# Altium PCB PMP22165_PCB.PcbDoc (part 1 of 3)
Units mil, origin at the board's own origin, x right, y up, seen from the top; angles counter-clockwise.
Board outline 3700 x 3000 mil, 4 copper layers (Top Layer, Signal Layer 1, Signal Layer 2, Bottom Layer), stack 61.634 mil thick; 232 components, 104 nets, 594 pads, 232 vias.
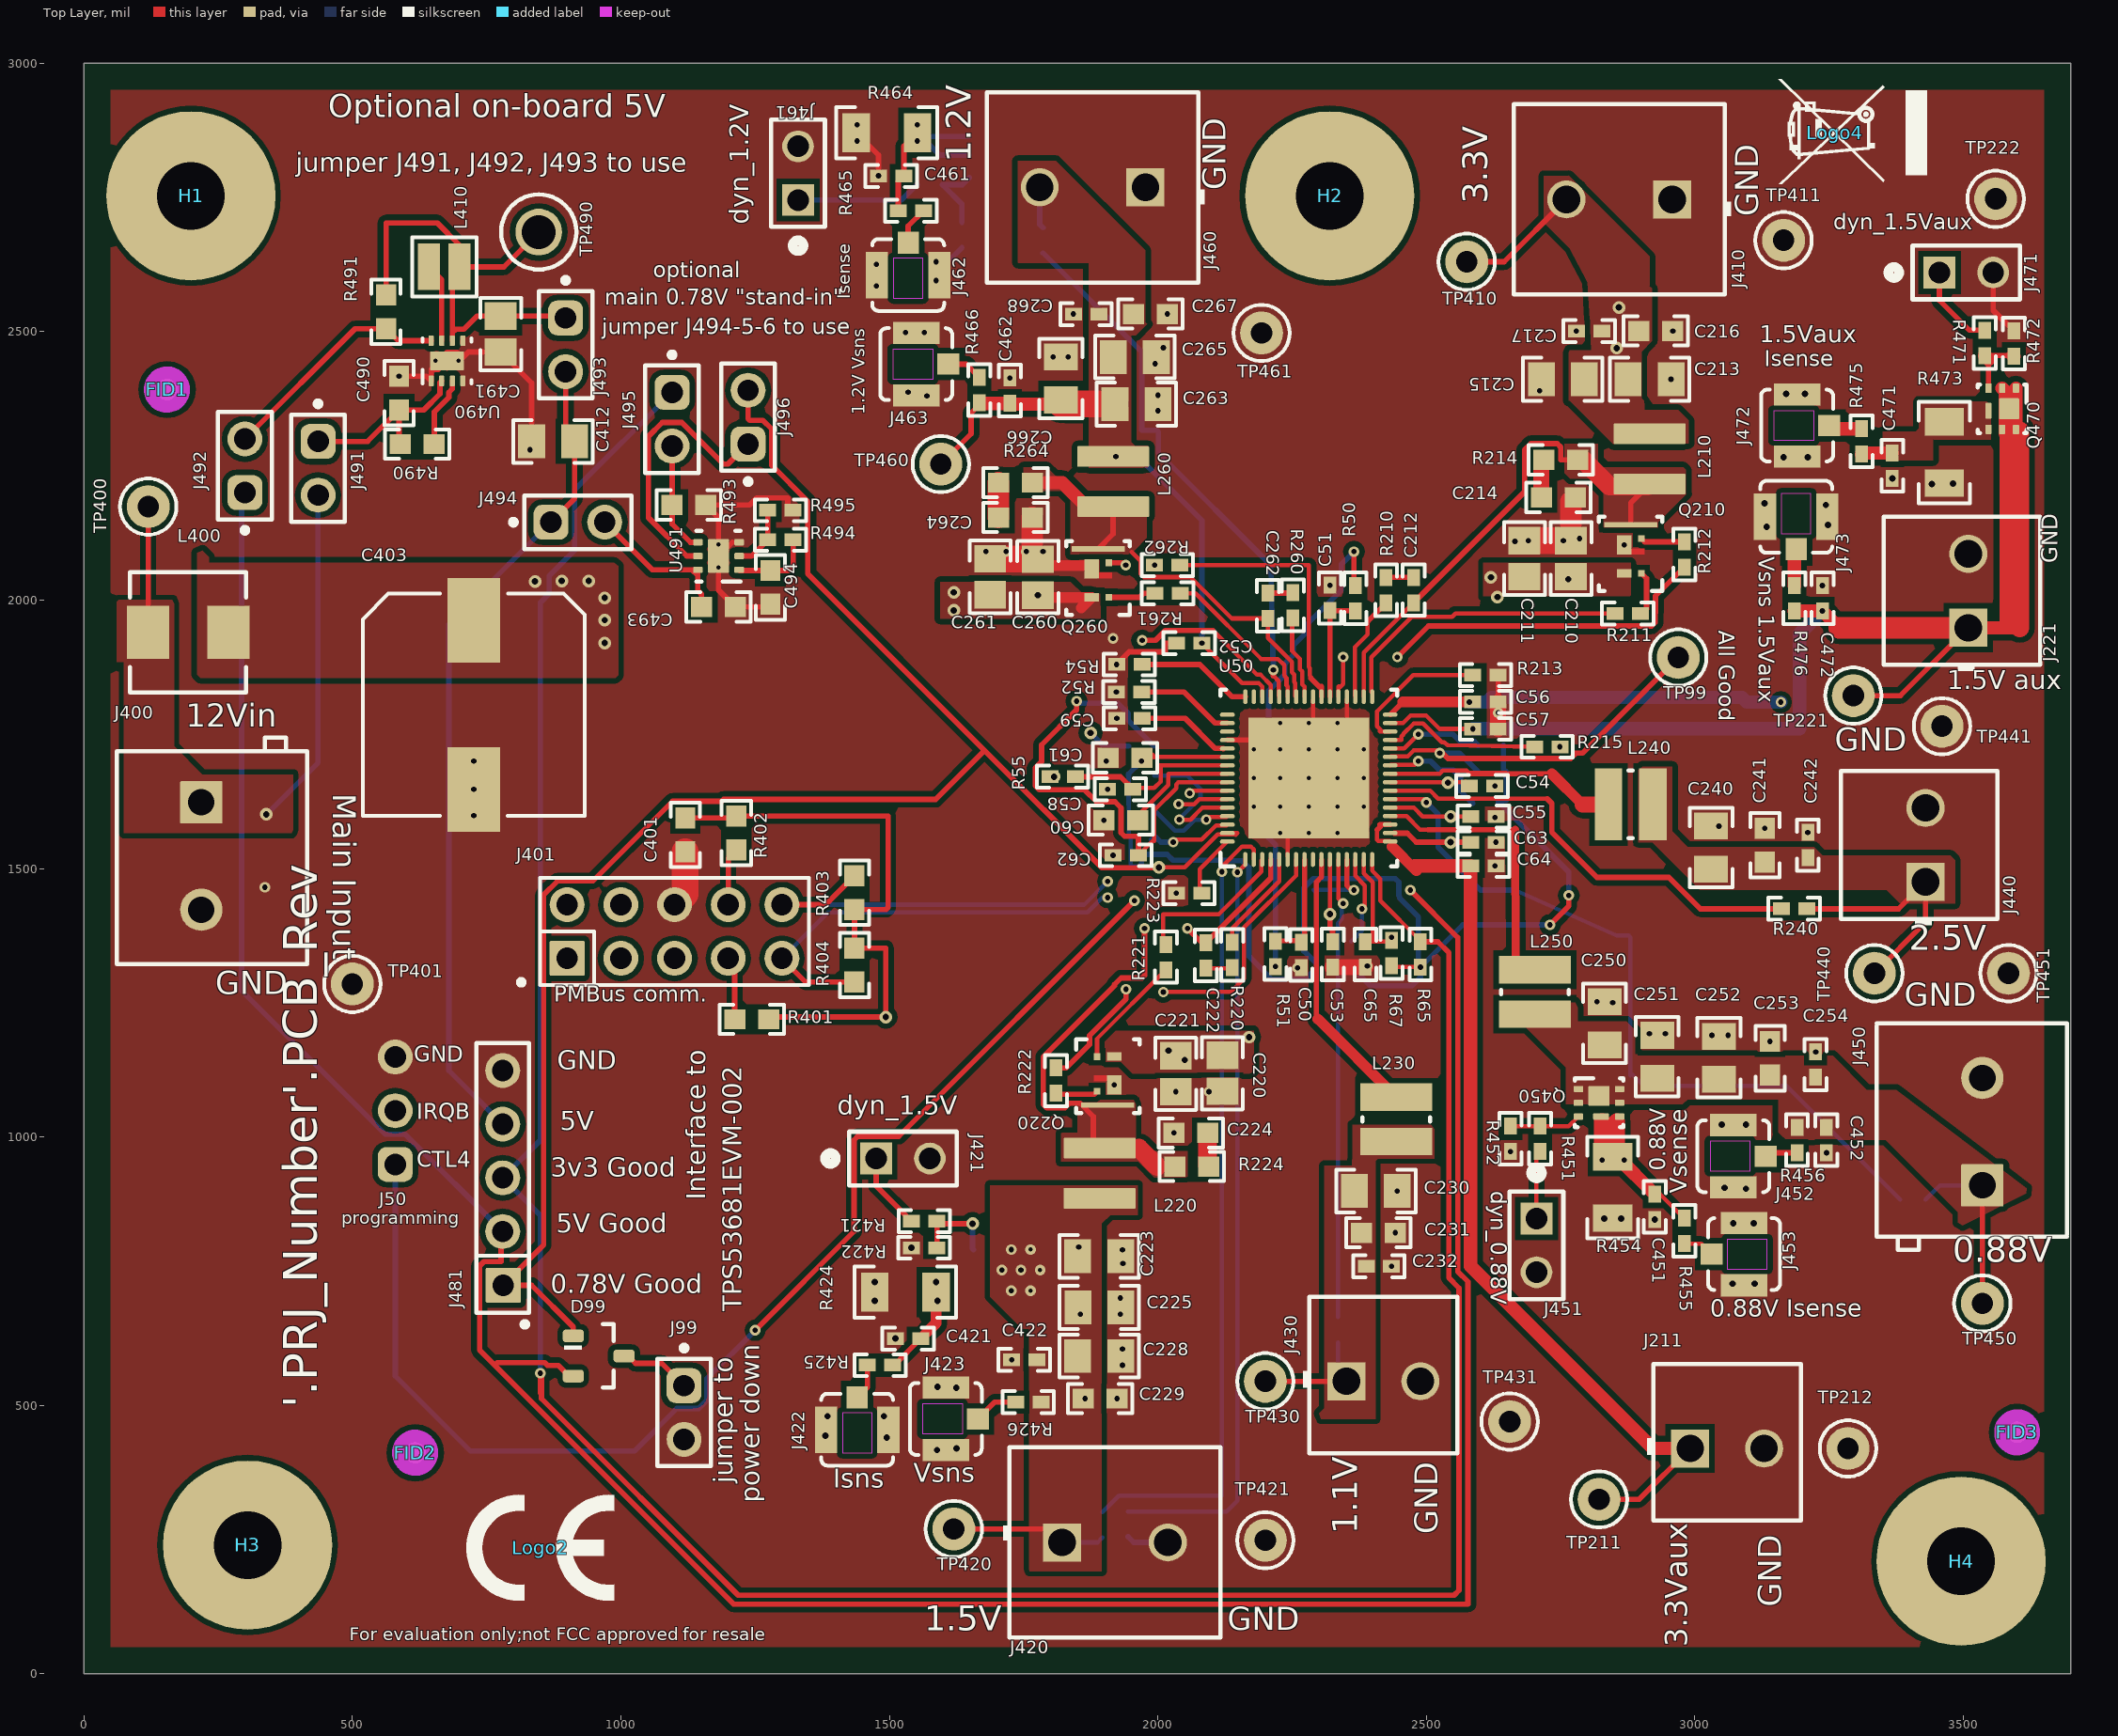
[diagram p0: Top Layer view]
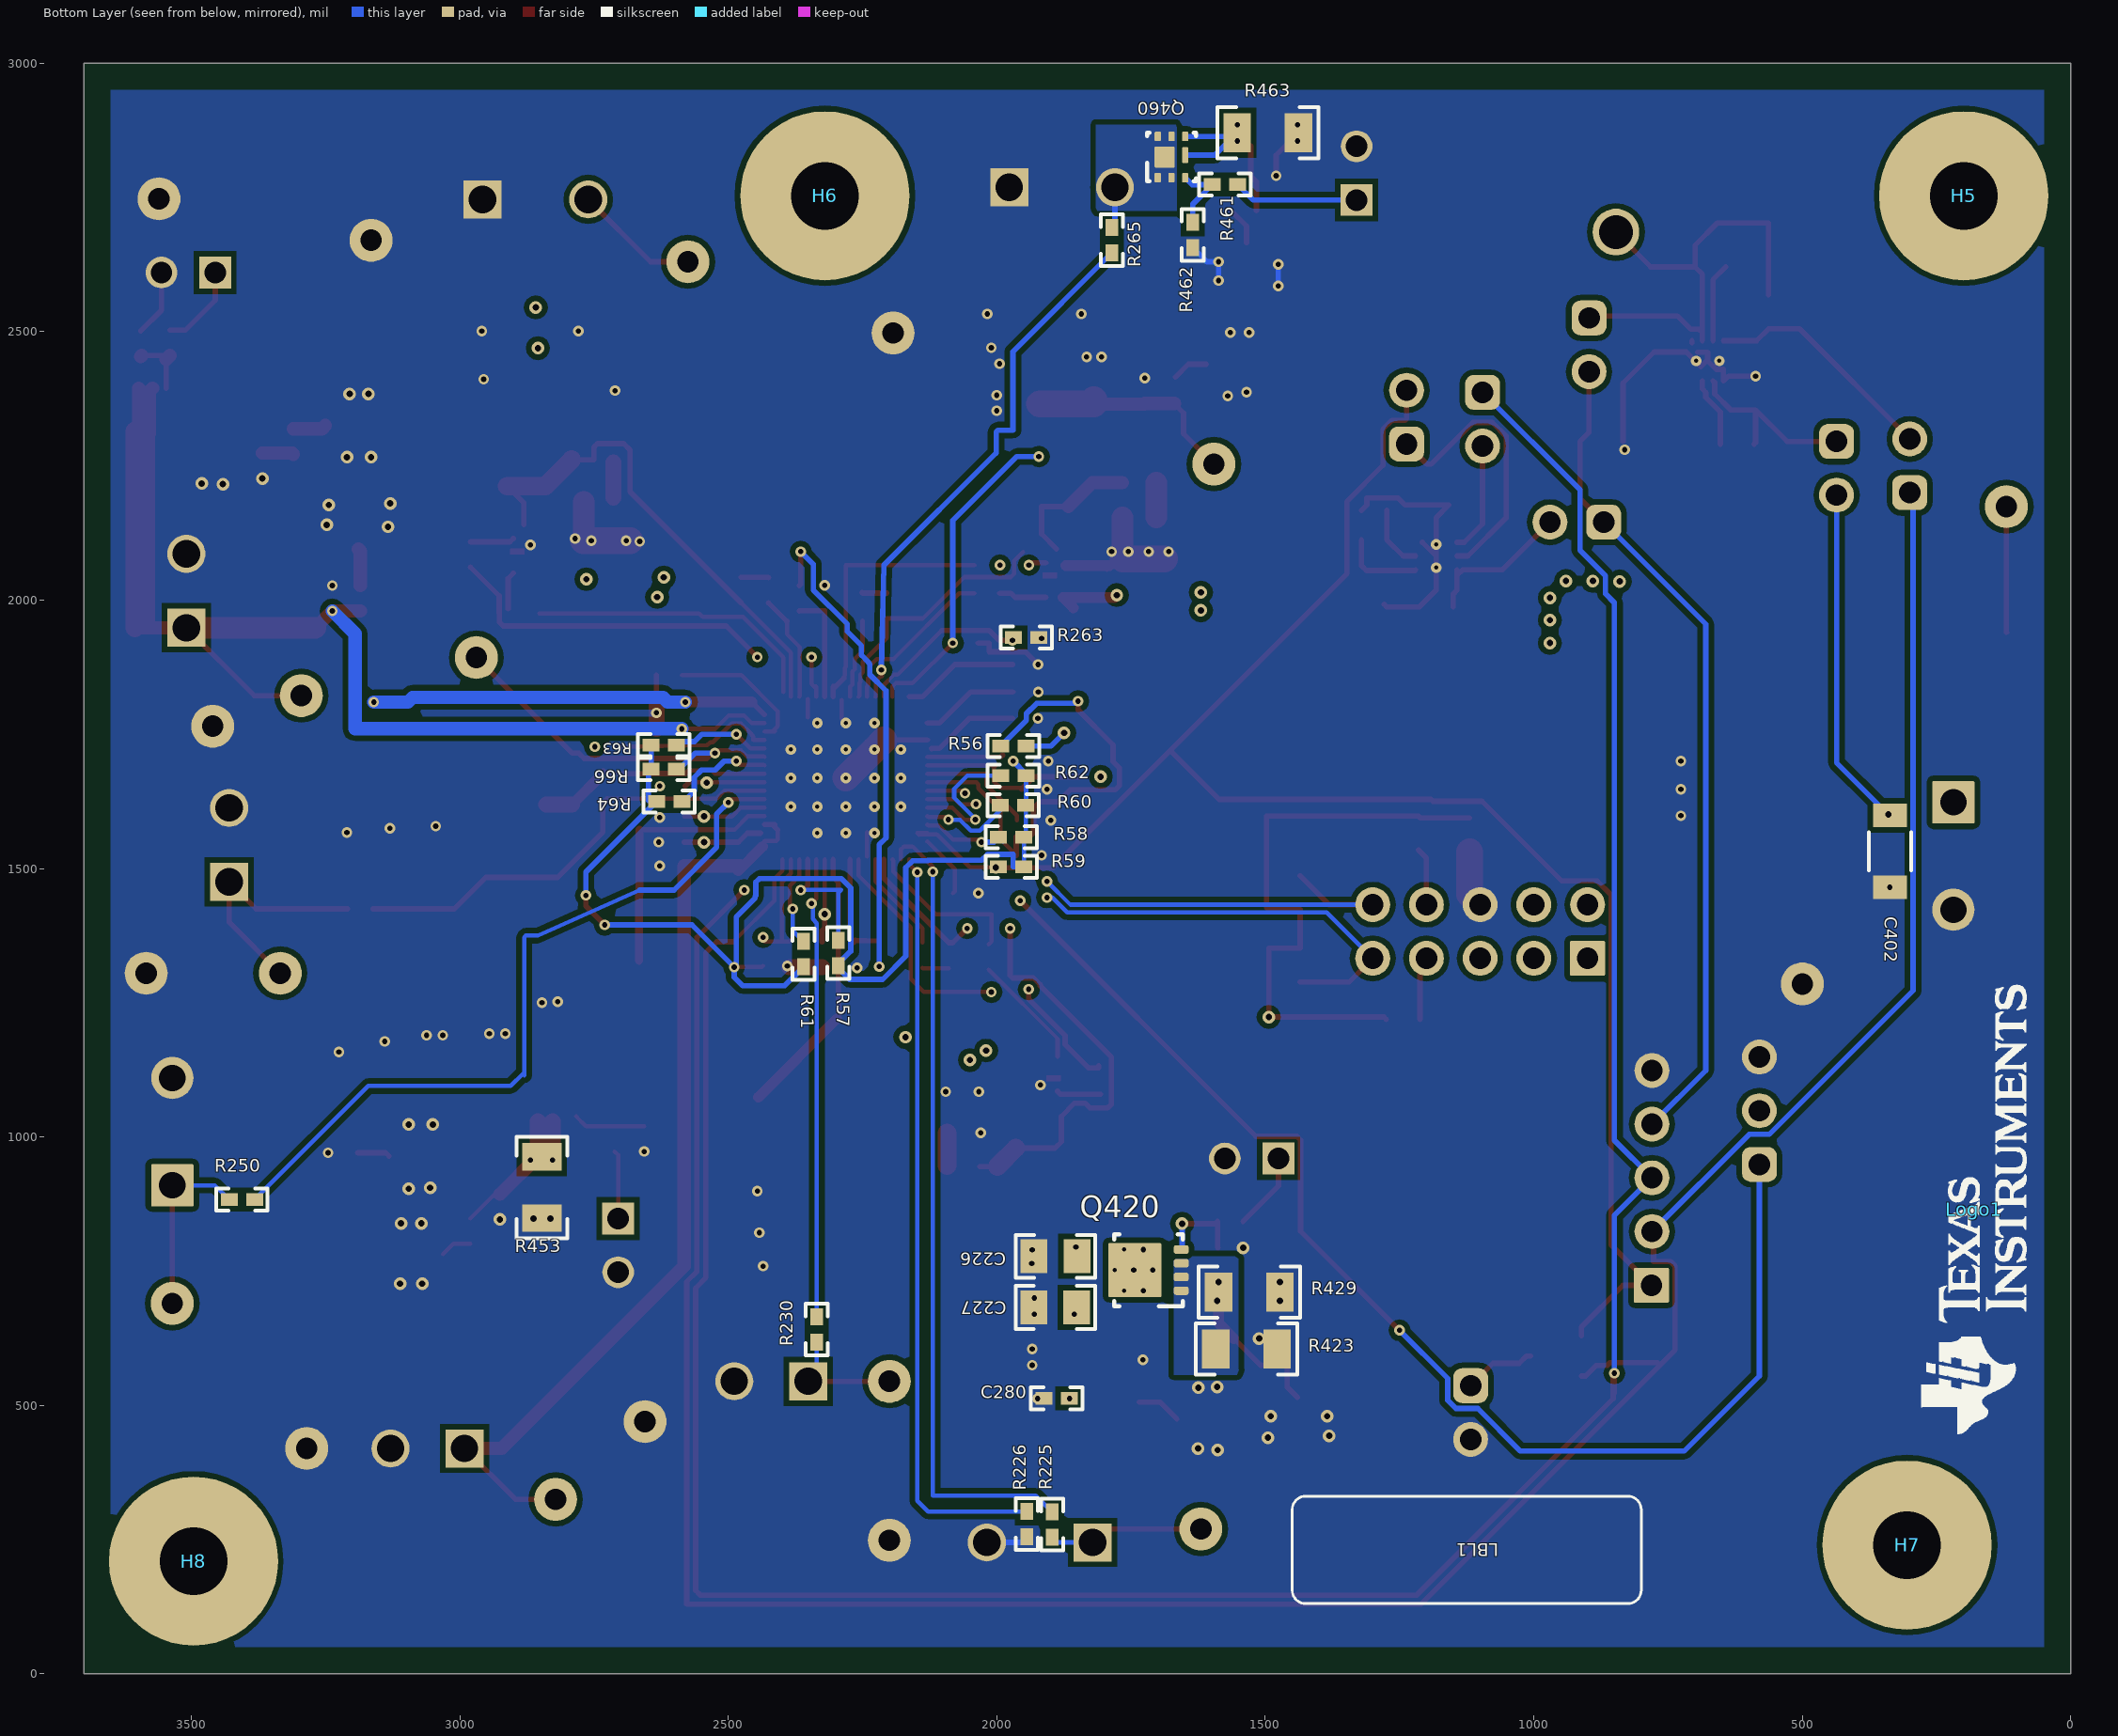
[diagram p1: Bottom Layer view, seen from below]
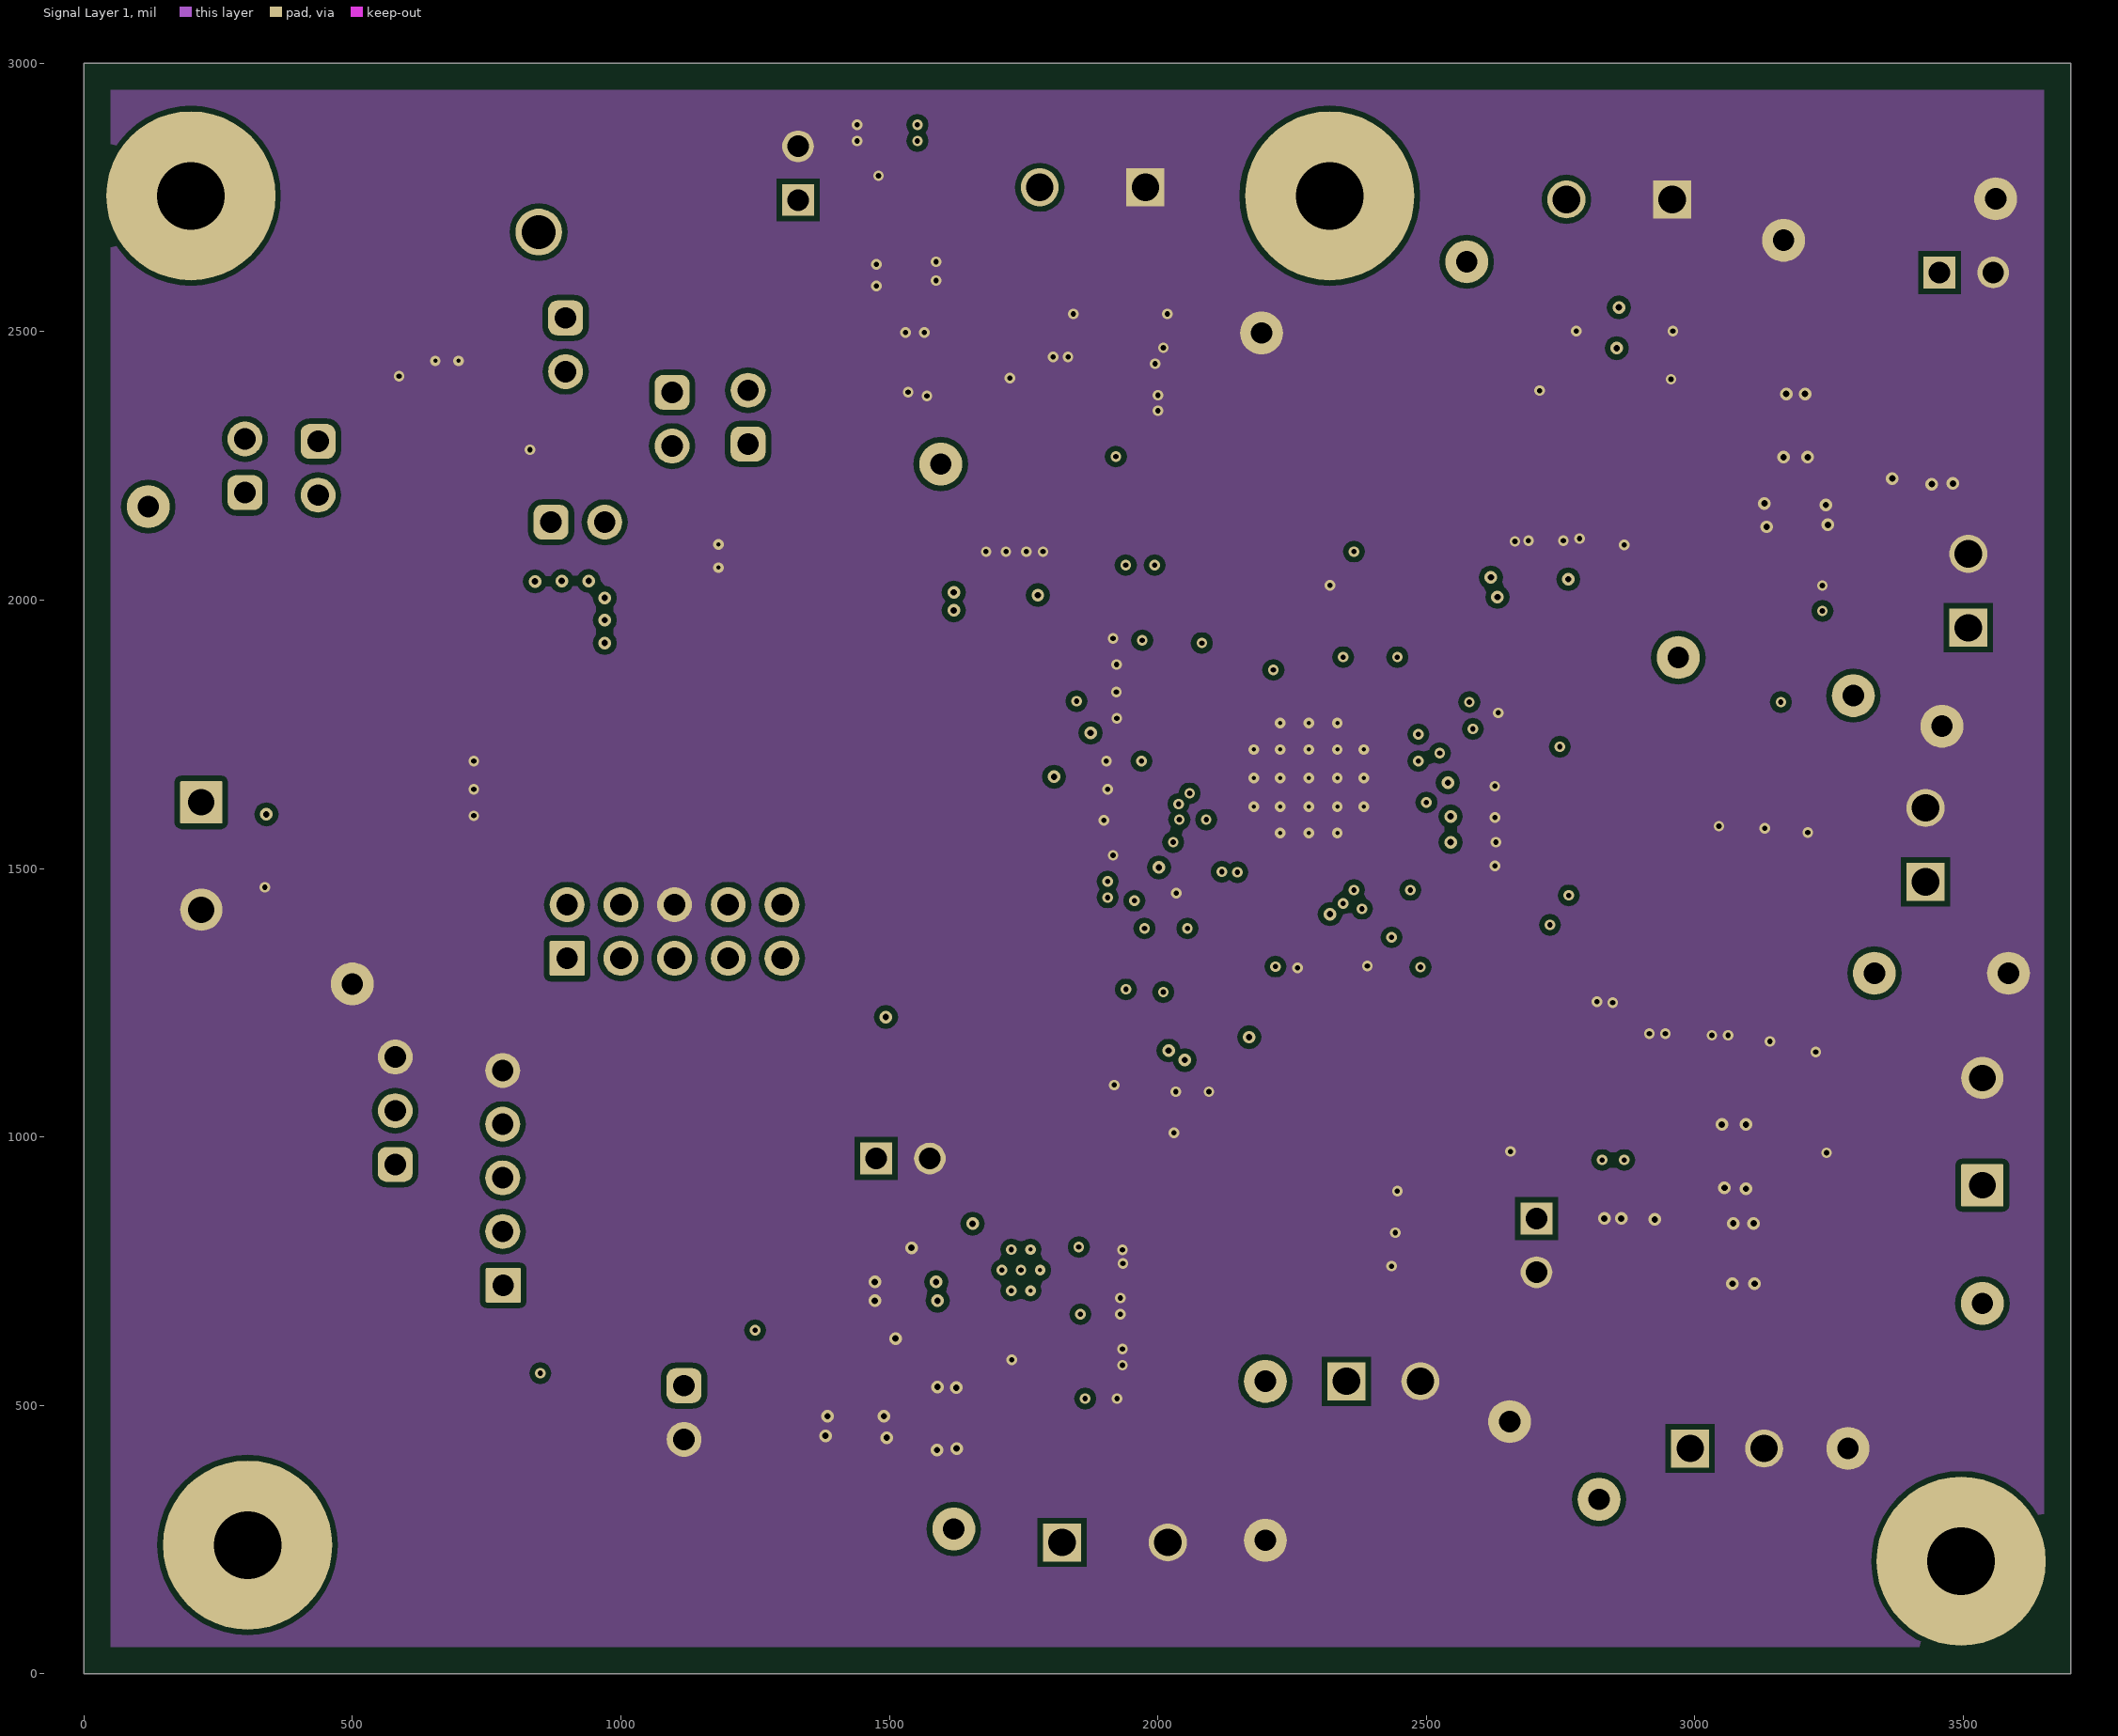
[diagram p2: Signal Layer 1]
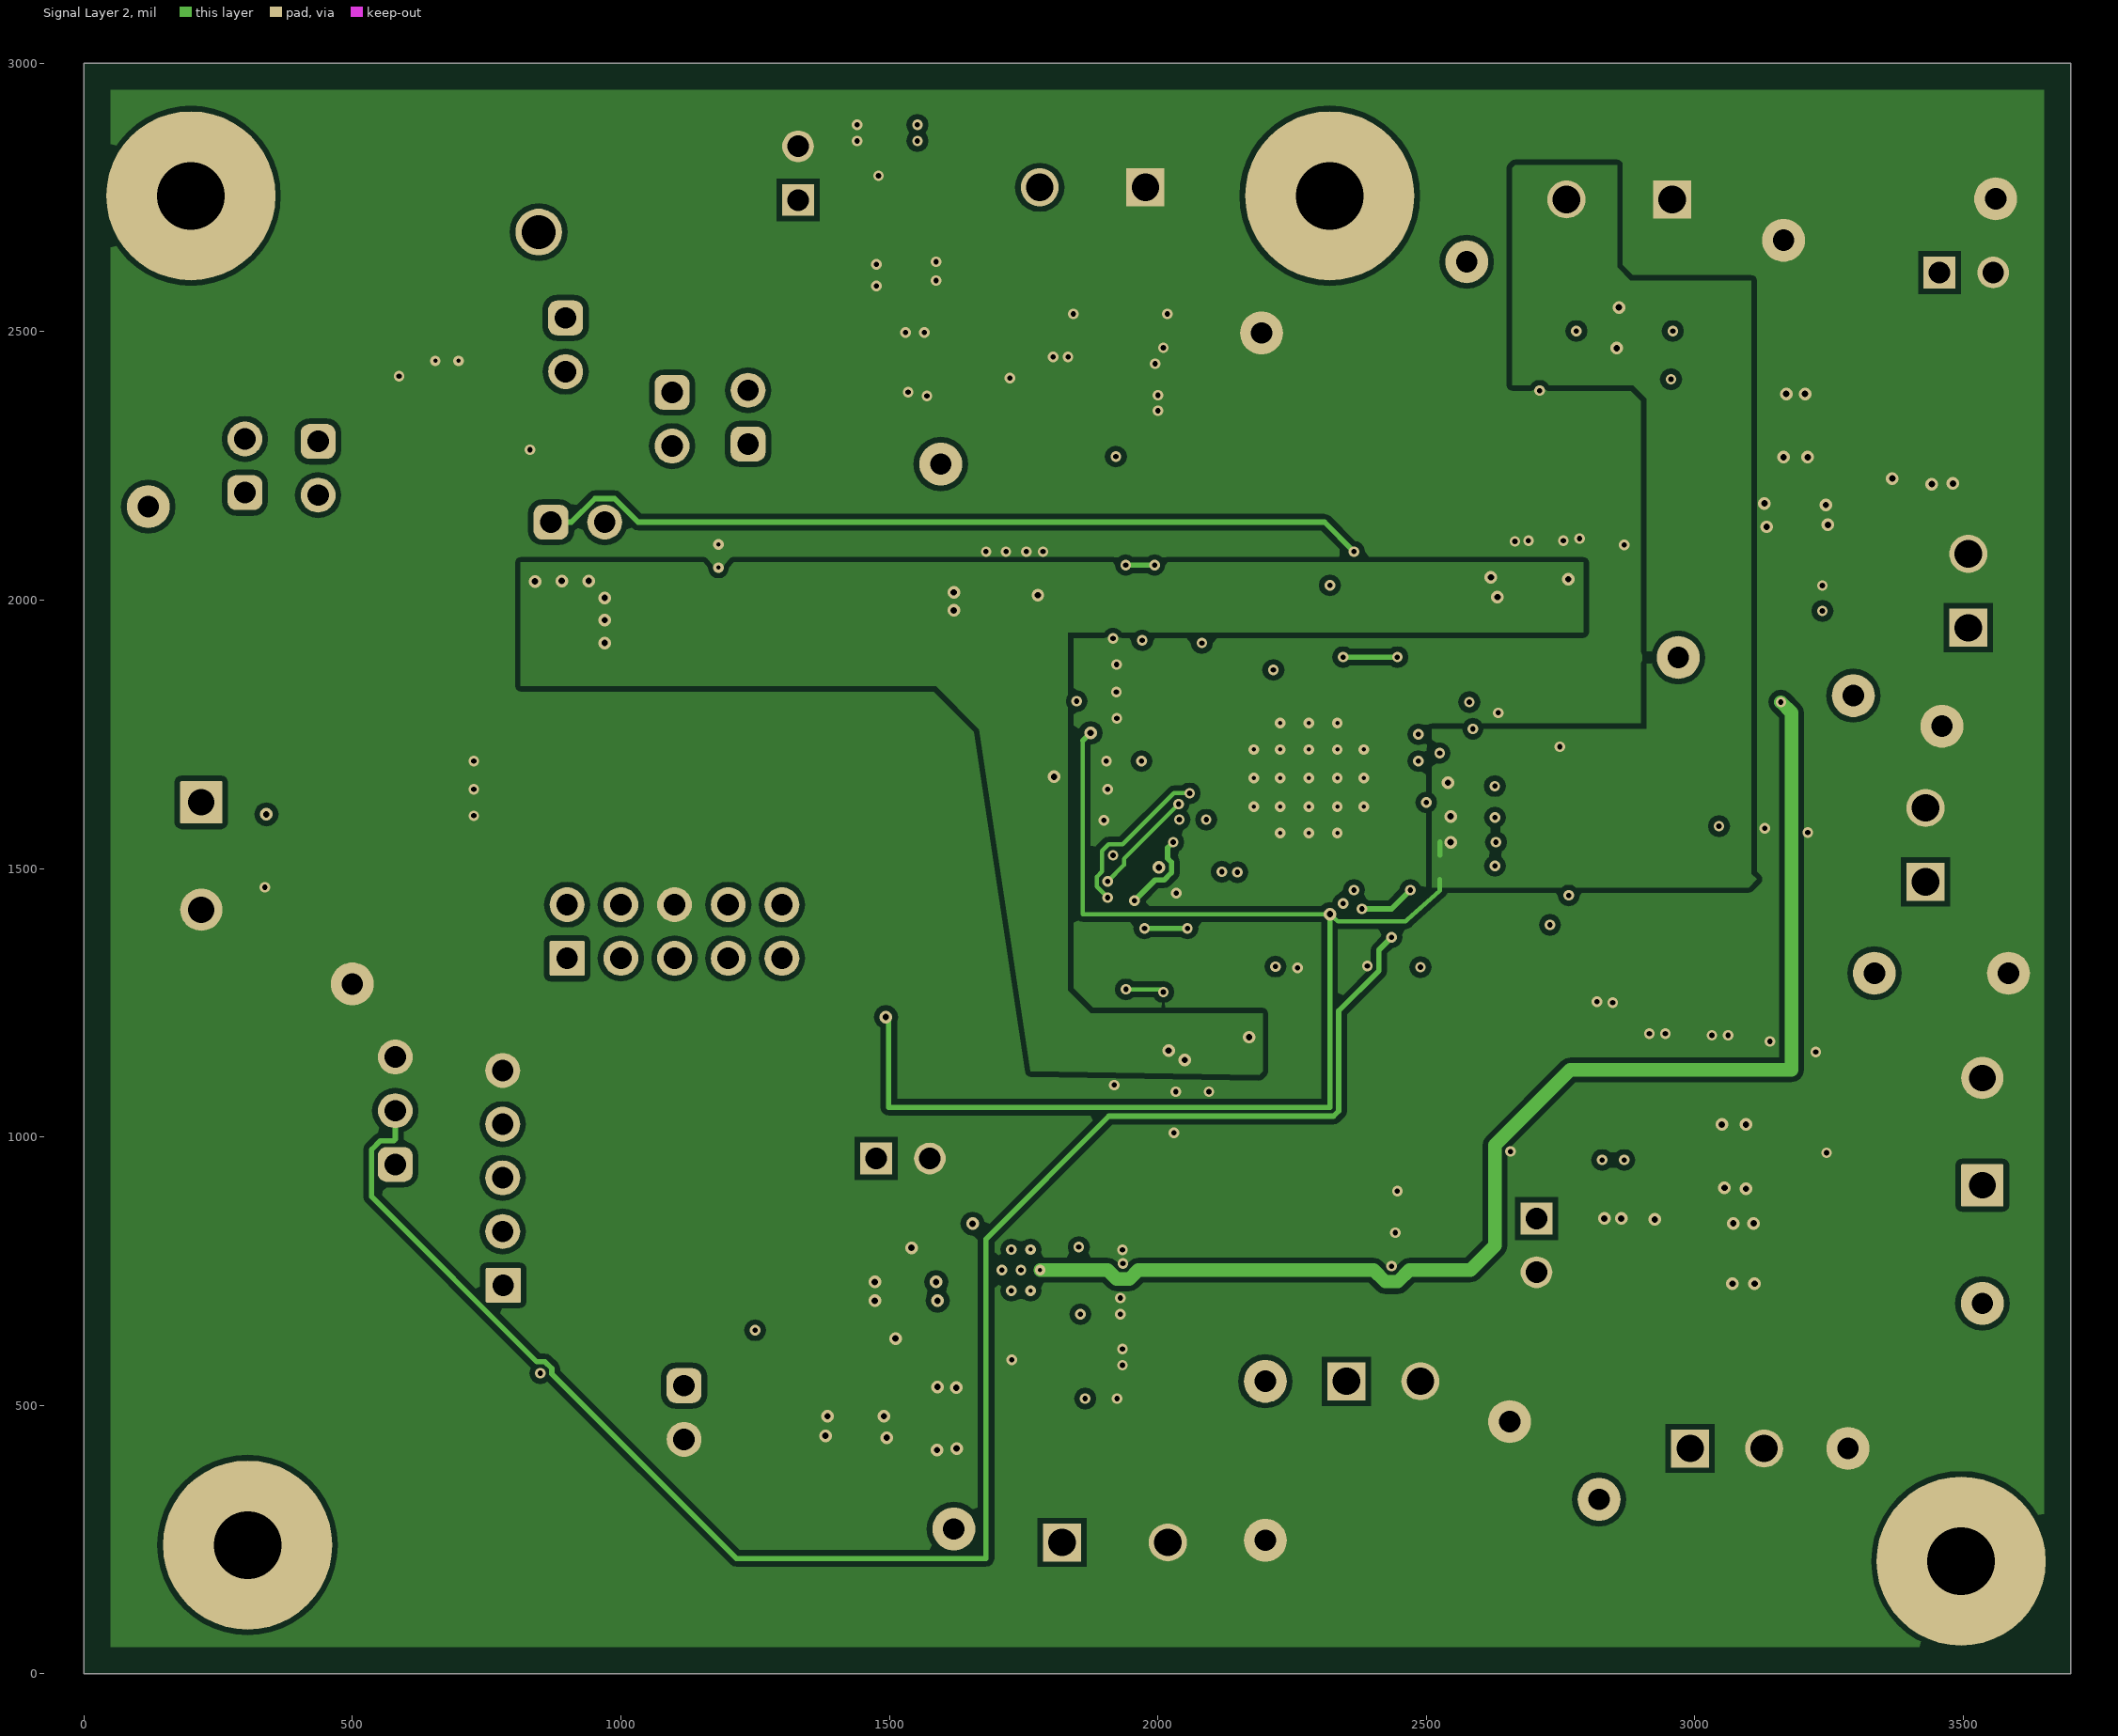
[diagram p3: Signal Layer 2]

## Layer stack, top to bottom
Top Solder: solder mask 0.4, Solder Resist, Dk 3.5
Top Layer: signal copper 1.4
Dielectric1: core 10, FR-4, Dk 4.8
Signal Layer 1: signal copper 1.417
Dielectric 2: prepreg 36, Dk 4.2
Signal Layer 2: signal copper 1.417
Dielectric 3: core 10, Dk 4.2
Bottom Layer: signal copper 1.4
Bottom Solder: solder mask 0.4, Solder Resist, Dk 3.5

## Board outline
0,0 3700,0 3700,3000 0,3000

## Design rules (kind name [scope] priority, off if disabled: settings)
AcuteAngle [All] p1: minimum=4.50000000000000E+0001 checktracksonly=FALSE
AssemblyTestPointUsage [All] p1: valid=2
BoardOutlineClearance BoardOutlineClearance_MountingHoles [OnCopper and InComponentClass('Mounting Holes')] p1: gap=39.37 ignorepadtopadclearanceinfootprint=FALSE
BoardOutlineClearance BoardOutlineClearance_Poly [OnCopper and IsPoly] p2: gap=50 ignorepadtopadclearanceinfootprint=FALSE
BoardOutlineClearance [OnCopper and Not InComponentClass('Logo') and not InComponentClass('FiducialMark') and not InRegion(1000,500,4000,800) and not InPoly] p3: gap=75 ignorepadtopadclearanceinfootprint=FALSE
Clearance Clearance_Keepouts [((IsTrack Or IsArc) And Not InPoly) And IsFree and IsKeepOut vs ((IsTrack Or IsArc) And Not InPoly) And IsFree and IsKeepOut] p1: gap=0 ignorepadtopadclearanceinfootprint=FALSE
Clearance Clearance_Poly [InPolygon] p2: gap=10 ignorepadtopadclearanceinfootprint=TRUE
Clearance Clearance_FiducialMark [IsKeepOut and InComponentClass('FiducialMark') vs IsPad and InComponentClass('FiducialMark')] p3: gap=0 ignorepadtopadclearanceinfootprint=FALSE
Clearance [All] p4: gap=5 ignorepadtopadclearanceinfootprint=TRUE
ComponentClearance ComponentClearance_MountingHoles_FiducialMarks [InComponentClass('Mounting Holes') vs InComponentClass('FiducialMark')] p1: gap=50 collisioncheckmode=3 verticalgap=10 showdistances=FALSE
ComponentClearance ComponentClearance_Shunt [InComponentClass('Header') vs InComponentClass('Shunt')] p2: gap=0 collisioncheckmode=3 verticalgap=0 showdistances=FALSE
ComponentClearance ComponentClearance_Logo [InComponentClass('Logo')] p3: gap=50 collisioncheckmode=3 verticalgap=10 showdistances=FALSE
ComponentClearance ComponentClearance_ScrewToNut [(HasFootprint('NY PMS 440 0025 PH')) vs (HasFootprint('Keystone_1902C'))] p4: gap=5 collisioncheckmode=3 verticalgap=10 showdistances=FALSE
ComponentClearance ComponentClearance_MountingHoles [InComponentClass('Mounting Holes')] p5: gap=100 collisioncheckmode=3 verticalgap=100000 showdistances=FALSE
ComponentClearance ComponentClearance_SmallPassives [HasFootprint('0201*') or HasFootprint('0402*') or HasFootprint('0508') or HasFootprint('0603*') or HasFootprint('0612') or HasFootprint('0805*') or HasFootprint('0815*') or HasFootprint('0830*') or HasFootprint('1206*') or HasFootprint('1210*') or HasFootprint('1808*') or HasFootprint('1812*') or HasFootprint('1825*') or HasFootprint('2010*') or HasFootprint('2220*') or HasFootprint('2225*') or HasFootprint('2512*') or HasFootprint('2728*') or HasFootprint('3518*') vs HasFootprint('0201*') or HasFootprint('0402*') or HasFootprint('0508') or HasFootprint('0603*') or HasFootprint('0612') or HasFootprint('0805*') or HasFootprint('0815*') or HasFootprint('0830*') or HasFootprint('1206*') or HasFootprint('1210*') or HasFootprint('1808*') or HasFootprint('1812*') or HasFootprint('1825*') or HasFootprint('2010*') or HasFootprint('2220*') or HasFootprint('2225*') or HasFootprint('2512*') or HasFootprint('2728*') or HasFootprint('3518*')] p6: gap=14.96 collisioncheckmode=3 verticalgap=10 showdistances=FALSE
ComponentClearance ComponentClearance_THtoSMT [IsThruComponent vs IsSMTComponent] p7: gap=40 collisioncheckmode=3 verticalgap=30 showdistances=FALSE
ComponentClearance ComponentClearance_THtoTH [IsThruComponent vs IsThruComponent] p8: gap=30 collisioncheckmode=3 verticalgap=30 showdistances=FALSE
ComponentClearance [All] p9: gap=30 collisioncheckmode=3 verticalgap=10 showdistances=FALSE
DiffPairsRouting [All] p1: maxlimit=100 minlimit=10 mostfreqgap=10 toplayer_minwidth=15 toplayer_maxwidth=15 toplayer_prefwidth=15 midlayer1_minwidth=15 midlayer1_maxwidth=15 midlayer1_prefwidth=15 midlayer2_minwidth=15 midlayer2_maxwidth=15 midlayer2_prefwidth=15 bottomlayer_minwidth=15 bottomlayer_maxwidth=15 bottomlayer_prefwidth=15 maxuncoupledlength=1000
FabricationTestPointUsage TestPointUsage [All] p1: valid=2 allowmultiple=FALSE
FabricationTestpoint Testpoint [All] p1: side=3 testpointundercomponent=TRUE minsize=40 maxsize=100 preferedsize=60 minholesize=0 maxholesize=40 preferedholesize=32 testpointgrid=1 allowsidetop=TRUE allowsidebottom=TRUE usegrid=TRUE gridtolerance=0.01
FanoutControl Fanout_LCC [IsLCC] p1: bgadir=Out bgaviamode=Centered fanoutstyle=Auto fanoutdirection=Alternating viagrid=1 // Fanout_LCC (Default Rule)
FanoutControl Fanout_BGA [IsBGA] p2: bgadir=Out bgaviamode=Centered fanoutstyle=Auto fanoutdirection=Alternating viagrid=1 // Fanout_BGA (Default Rule)
FanoutControl Fanout_Default [All] p4: bgadir=Out bgaviamode=Centered fanoutstyle=Auto fanoutdirection=Alternating viagrid=1 // Fanout_Default (Default Rule)
FanoutControl Fanout_Small [(CompPinCount < 5)] p5: bgadir=Out bgaviamode=Centered fanoutstyle=Auto fanoutdirection=OutThenIn viagrid=1 // Fanout_Small (Default Rule)
HoleSize [All] p1: absolutevalues=TRUE maxlimit=251 minlimit=7.87 maxpercent=80.000 minpercent=20.000
MinimumAnnularRing MinimumAnnularRing_ThermalPadVias [IsVia and InAnyComponent] p1: minimumring=4
MinimumAnnularRing [All] p2: minimumring=4
MinimumSolderMaskSliver MinimumSolderMaskSliver_PadPad [IsPad vs IsPad] p1: minsoldermaskwidth=1.5
MinimumSolderMaskSliver MinimumSolderMaskSliver_Via [IsVia] p2: minsoldermaskwidth=1.5
MinimumSolderMaskSliver MinimumSolderMaskSliver_Logo [InComponentClass('Logo') vs InComponentClass('Logo')] p3: minsoldermaskwidth=0.7
MinimumSolderMaskSliver [All] p4: minsoldermaskwidth=3.94
PlaneClearance [All] p1: clearance=10
PlaneConnect [All] p1: planeconnectstyle=Relief reliefexpansion=10 reliefentries=4 reliefconductorwidth=10 reliefairgap=10
PolygonConnect [All] p1: connectstyle=Direct reliefconductorwidth=10 reliefentries=4 polygonreliefangle="90 Angle" airgapwidth=10
RoutingVias ThermalPadVias [IsVia and InAnyComponent] p1: holewidth=7.87 width=19.68 viastyle="Through Hole" minholewidth=7.87 minwidth=19.68 maxholewidth=12.99 maxwidth=23.62
RoutingVias [All] p2: holewidth=10 width=18 viastyle="Through Hole" minholewidth=10 minwidth=18 maxholewidth=40 maxwidth=65
SMDEntry [All] p1: side=TRUE corner=TRUE anyangle=FALSE
SMDToCorner [All] p1: distance=50000
SilkToBoardRegionClearance [Not ((IsComment or IsDesignator) And (Hide <> 'False')) and not InRegion(1000,500,4000,800)] p1:
SilkToSilkClearance SilkToSilkClearance_Pb-FreeLogo [(HasFootprint('Pb-Free_Overlay_Medium') OR HasFootprint('Pb-Free_Overlay_Small')) vs (HasFootprint('Pb-Free_Overlay_Medium') OR HasFootprint('Pb-Free_Overlay_Small'))] p1: silktosilkclearance=0
SilkToSilkClearance [All] p2: silktosilkclearance=0
SilkToSolderMaskClearance SilkToComponentPadClearance [(IsPad or IsFill or IsRegion) and InAnycomponent] p1: minsilkscreentomaskgap=5 clearancetoexposedcopper=TRUE
SilkToSolderMaskClearance "Silk to Solder Mask Opening" [All] p2: minsilkscreentomaskgap=3.94 clearancetoexposedcopper=FALSE
SolderMaskExpansion [All] p1: expansion=4
UnRoutedNet [All] p1: checkbadconnections=TRUE
Width [All] p1: maxlimit=100 minlimit=5 preferedwidth=10 checkconnectedcopper=TRUE
13 further rules are at their usual default settings.

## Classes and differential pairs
component class TPS650861_Bucks: C210 C211 C212 C213 C214 C215 C216 C217 C220 C221 C222 C223 C224 C225 C226 C227 C228 C229 C260 C261 C262 C263 C264 C265 C266 C267 C268 C280 C403 J410 J420 J460 L210 L220 L260 Q210 Q220 Q260 R210 R211 R212 R213 R214 R215 R220 R221 R222 R223 R224 R225 R226 R260 R261 R262 R263 R264 R265 TP410 TP411 TP420 TP421 TP460 TP461
component class TPS650861&Outputs: C50 C51 C52 C53 C54 C55 C56 C57 C58 C59 C60 C61 C62 C63 C64 C65 C230 C231 C232 C240 C241 C242 C250 C251 C252 C253 C254 D99 J50 J99 J211 J221 J430 J440 J450 J481 L230 L240 L250 R50 R51 R52 R54 R55 R56 R57 R58 R59 R60 R61 R62 R63 R64 R65 R66 R67 R230 R240 R250 TP99 TP211 TP212 TP221 TP222 TP430 TP431 TP440 TP441 TP450 TP451 U50
component class Header: J50 J99 J401 J421 J451 J461 J471 J481 J491 J492 J493 J494 J495 J496
component class "Mounting Holes": H1 H2 H3 H4
component class Logo: Logo1
component class PMP22165_Hardware: C401 C402 C412 C421 C422 C451 C452 C461 C462 C471 C472 C490 C491 C493 C494 FID1 FID2 FID3 H1 H2 H3 H4 H5 H6 H7 H8 J400 J401 J421 J422 J423 J451 J452 J453 J461 J462 J463 J471 J472 J473 J491 J492 J493 J494 J495 J496 L400 L410 LBL1 Logo1 Logo2 Logo4 Q420 Q450 Q460 Q470 R401 R402 R403 R404 R421 R422 R423 R424 R425 R426 R429 R451 R452 R453 R454 R455 R456 R461 R462 R463 R464 R465 R466 R471 R472 R473 R475 R476 R490 R491 R493 R494 R495 TP400 TP401 TP490 U490 U491 ZZ1 ZZ2 ZZ3 ZZ4
component class FiducialMark: FID1 FID2 FID3
component class AssemblyNote: ZZ1 ZZ2 ZZ3 ZZ4
component class Label: LBL1

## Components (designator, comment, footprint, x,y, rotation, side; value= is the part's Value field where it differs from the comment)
C50 "Capacitor" 0402 2266.78,1339.09 r270 top value=2.2uF
C51 "Capacitor" 0402 2320.26,2003.82 r90 top value=2.2uF
C52 "GRM155R61A106ME11" 0402 2058.16,1920 r180 top value=10uF
C53 "GRM155R61A106ME11" 0402 2325.33,1340 r270 top value=10uF
C54 "GRM155R61A106ME11" 0402 2603.78,1653.46 r0 top value=10uF
C55 "GRM155R61A106ME11" 0402 2605.94,1597.09 r0 top value=10uF
C56 "Capacitor" 0402 2610,1810 r0 top value=1uF
C57 "Capacitor" 0402 2610,1760 r0 top value=1uF
C58 "Capacitor" 0402 1930,1647.52 r180 top value=1uF
C59 "Capacitor" 0402 1947.18,1779.59 r180 top value=0.1uF
C60 "Capacitor" 0603 1931.08,1590 r180 top value=4.7uF
C61 "Capacitor" 0603 1938.5,1706.29 r180 top value=4.7uF
C62 "Capacitor" 0402 1940,1524.59 r180 top value=1uF
C63 "Capacitor" 0402 2605.94,1549.02 r0 top value=1uF
C64 "Capacitor" 0402 2605.94,1505 r0 top value=0.1uF
C65 "Capacitor" 0402 2386.46,1340 r270 top value=1uF
C210 "C2012X5R1C226M125AC" 0805 2769.18,2077.27 r90 top value=22uF
C211 "C2012X5R1C226M125AC" 0805 2682.48,2077.27 r90 top value=22uF
C212 "Capacitor" 0402 2476.1,2018.62 r90 top value=0.1uF
C213 "GRM21BR60J476ME15L" 0805_HV 2915.48,2411.11 r0 top value=47uF
C214 "DNP" 0603 2745.48,2191.11 r0 top value=330pF
C215 "GRM21BR60J476ME15L" 0805_HV 2753.99,2411.11 r180 top value=47uF
C216 "Capacitor" 0603 2927.24,2501.11 r0 top value=4.7uF
C217 "Capacitor" 0402 2802.87,2501.11 r180 top value=0.1uF
C220 "C2012X5R1C226M125AC" 0805 2120.24,1118.62 r270 top value=22uF
C221 "C2012X5R1C226M125AC" 0805 2033.43,1117.66 r270 top value=22uF
C222 "Capacitor" 0402 2089.5,1338 r270 top value=0.1uF
C223 "GRM21BR60J476ME15L" 0805_HV 1890.77,777.7 r0 top value=47uF
C224 "DNP" 0603 2061.34,1007.66 r180 top value=330pF
C225 "GRM21BR60J476ME15L" 0805_HV 1891.08,682.7 r0 top value=47uF
C226 "GRM21BR60J476ME15L" 0805_HV 1890.77,777.7 r0 bottom value=47uF
C227 "GRM21BR60J476ME15L" 0805_HV 1891.08,682.7 r0 bottom value=47uF
C228 "GRM21BR60J476ME15L" 0805_HV 1890.77,592.04 r0 top value=47uF
C229 "Capacitor" 0603 1892.65,512.91 r0 top value=4.7uF
C230 "GRM21BR60J476ME15L" 0805_HV 2405.83,899.46 r0 top value=47uF
C231 "Capacitor" 0603 2410.4,821.62 r0 top value=4.7uF
C232 "Capacitor" 0402 2411.46,759.46 r0 top value=0.1uF
C240 "GRM21BR60J476ME15L" 0805_HV 3030.16,1538.96 r90 top value=47uF
C241 "Capacitor" 0603 3130.16,1543.53 r90 top value=4.7uF
C242 "Capacitor" 0402 3210.16,1543.53 r90 top value=0.1uF
C250 "GRM21BR60J476ME15L" 0805_HV 2831.59,1211.77 r90 top value=47uF
C251 "GRM21BR60J476ME15L" 0805_HV 2929.85,1149.34 r90 top value=47uF
C252 "GRM21BR60J476ME15L" 0805_HV 3044.85,1147.53 r90 top value=47uF
C253 "Capacitor" 0603 3139.85,1146.52 r90 top value=4.7uF
C254 "Capacitor" 0402 3224.85,1134.7 r90 top value=0.1uF
C260 "C2012X5R1C226M125AC" 0805 1776.48,2042.6 r90 top value=22uF
C261 "C2012X5R1C226M125AC" 0805 1687.64,2043.33 r90 top value=22uF
C262 "Capacitor" 0402 2205,1989.3 r90 top value=0.1uF
C263 "GRM21BR60J476ME15L" 0805_HV 1960,2364.97 r0 top value=47uF
C264 "DNP" 0603 1734.68,2153.63 r0 top value=330pF
C265 "GRM21BR60J476ME15L" 0805_HV 1957,2452.73 r0 top value=47uF
C266 "GRM21BR60J476ME15L" 0805_HV 1819.41,2412.73 r90 top value=47uF
C267 "Capacitor" 0603 1985.99,2532.73 r0 top value=4.7uF
C268 "Capacitor" 0402 1866.22,2532.73 r180 top value=0.1uF
C280 "Capacitor" 0402 1888.22,512.91 r0 bottom value=0.1uF
C401 "06035C104KAT2A" 0603 1120,1562.67 r270 top value=0.1uF
C402 "GRM31CR61C226KE15L" 1206_180 336.96,1531.93 r90 bottom value=22uF
C403 "EEHZA1V271P" SM_RADIAL_10BMM 726.14,1805 r270 top value=270uF
C412 "C2012X5R0J226M085AB" 0805_HV 873.91,2295.44 r180 top value=22uF
C421 "GCM155R71H104KE02D" 0402 1535,624.69 r180 top value=0.1uF
C422 "GCM155R71H104KE02D" 0402 1751.38,585 r180 top value=0.1uF
C451 "Capacitor" 0402 2925,870 r270 top value=0.1uF
C452 "GCM155R71H104KE02D" 0402 3245,994.24 r270 top value=0.1uF
C461 "Capacitor" 0402 1503.5,2790 r180 top value=0.1uF
C462 "Capacitor" 0402 1724.3,2389.97 r90 top value=0.1uF
C471 "Capacitor" 0402 3367.59,2250 r270 top value=0.1uF
C472 "Capacitor" 0402 3237.41,2003.26 r90 top value=0.1uF
C490 "C1608X5R1E106M080AC" 0603 587.11,2385.44 r90 top value=10uF
C491 "C2012X5R1E106K125AB" 0805 776.14,2495.44 r270 top value=10uF
C493 "CGA3E3X5R1A225K080AB" 0603 1181.87,1987.03 r0 top value=2.2uF
C494 "CGA3E3X5R1A225K080AB" 0603 1278.54,2023.49 r270 top value=2.2uF
D99 "BAT54C-7-F" SOT-23 958.65,592.17 r0 top value=30V
FID1 "Fiducial" Fiducial10-20 155,2391.97 r0 top
FID2 "Fiducial" Fiducial10-20 617.11,411.93 r0 top
FID3 "Fiducial" Fiducial10-20 3600,450 r0 top
H1 "NY PMS 440 0025 PH" "NY PMS 440 0025 PH" 199.47,2752.88 r0 top locked
H2 "NY PMS 440 0025 PH" "NY PMS 440 0025 PH" 2320,2752.88 r0 top locked
H3 "NY PMS 440 0025 PH" "NY PMS 440 0025 PH" 305,240 r0 top locked
H4 "NY PMS 440 0025 PH" "NY PMS 440 0025 PH" 3495.63,210 r0 top locked
H5 "1902C" Keystone_1902C 199.47,2752.88 r180 bottom locked
H6 "1902C" Keystone_1902C 2320,2752.88 r180 bottom locked
H7 "1902C" Keystone_1902C 305,240 r180 bottom locked
H8 "1902C" Keystone_1902C 3495.63,210 r180 bottom locked
J50 "TSW-103-07-G-S" TSW-103-07-G-S 580,1048.89 r90 top
J99 "TSW-102-07-G-S" TSW-102-07-G-S 1117.74,486.91 r270 top
J211 "691214110002" Wurth_691214110002 3060,420 r0 top
J221 "691214110002" Wurth_691214110002 3509.1,2017.23 r90 top
J400 "ED120/2DS" On-Shore_ED120_2DS 218.85,1523.17 r270 top
J401 "TSW-105-07-G-D" TSW-105-07-G-D 1100,1382.67 r0 top
J410 "Receptacle_2x1" Phoenix_1935776 2859.08,2746.11 r180 top
J420 "Receptacle_2x1" Phoenix_1935776 1920,245 r0 top
J421 "5-146261-1" CONN_5-146261-1 1525.28,960 r0 top
J422 "U.FL-R-SMT-1(01)" CONN_UFL-R-SMT-1 1440,455 r270 top
J423 "U.FL-R-SMT-1(01)" CONN_UFL-R-SMT-1 1605,475 r180 top
J430 "691214110002" Wurth_691214110002 2420,545 r0 top
J440 "691214110002" Wurth_691214110002 3429.26,1543.9 r90 top
J450 "ED120/2DS" On-Shore_ED120_2DS 3535.16,1010 r90 top
J451 "Header_2x1" CONN_5-146261-1 2705,798.1 r270 top
J452 "U.FL-R-SMT-1(01)" CONN_UFL-R-SMT-1 3091.43,781.9 r0 top
J453 "U.FL-R-SMT-1(01)" CONN_UFL-R-SMT-1 3071.57,964.24 r180 top
J460 "Receptacle_2x1" Phoenix_1935776 1878.41,2768.63 r180 top
J461 "Header_2x1" CONN_5-146261-1 1330,2795 r90 top
J462 "U.FL-R-SMT-1(01)" CONN_UFL-R-SMT-1 1535,2605.44 r270 top
J463 "U.FL-R-SMT-1(01)" CONN_UFL-R-SMT-1 1550,2439.35 r180 top
J471 "Header_2x1" CONN_5-146261-1 3505.33,2610 r0 top
J472 "U.FL-R-SMT-1(01)" CONN_UFL-R-SMT-1 3190.15,2325 r180 top
J473 "U.FL-R-SMT-1(01)" CONN_UFL-R-SMT-1 3188.5,2155.03 r90 top
J481 "TSW-105-07-G-S" TSW-105-07-X-S 780,923.92 r90 top
J491 "TSW-102-07-G-S" TSW-102-07-G-S 436.25,2245.44 r270 top
J492 "TSW-102-07-G-S" TSW-102-07-G-S 300,2250 r90 top
J493 "TSW-102-07-G-S" TSW-102-07-G-S 897.17,2475.44 r270 top
J494 "TSW-102-07-G-S" TSW-102-07-G-S 920,2145 r0 top
J495 "TSW-102-07-G-S" TSW-102-07-G-S 1095.38,2336.72 r270 top
J496 "TSW-102-07-G-S" TSW-102-07-G-S 1236.87,2340.66 r90 top
L210 "XAL4020-102MEB" XAL4020 2915.48,2262.76 r90 top value=1uH
L220 "XAL4020-102MEB" XAL4020 1891.49,932.66 r270 top value=1uH
L230 "744383360047" WE-MAPI_3020 2443.54,1032.97 r270 top value=470nH
L240 "744383360047" WE-MAPI_3020 2880.48,1619.17 r0 top value=470nH
L250 "744383360047" WE-MAPI_3020 2702.01,1270 r270 top value=470nH
L260 "XAL4020-102MEB" XAL4020 1916.69,2220.66 r90 top value=1uH
L400 "HCB65-550X" HCB65-550X 194.3,1940 r0 top value=55nH
L410 "XPL2010-222MLB" XPL2010 671.14,2620.44 r0 top value=2.2uH
LBL1 "THT-14-423-10" Label_650x200 1125,231 r0 bottom
Logo1 "Texas Instruments" TI_Stacked_Overlay_Small 180.49,865 r90 bottom
Logo2 "CE Mark" CE_Mark_5mm 850,235 r0 top
Logo4 "WEEE logo" WEEE_Minimum 3260,2870.56 r90 top
Q210 "CSD87381P" MPC0005A_100um 2880.48,2086.11 r180 top
Q220 "CSD87381P" MPC0005A_100um 1906.61,1113.45 r0 top
Q260 "CSD87381P" MPC0005A_100um 1888.88,2041.07 r180 top
Q420 "MOSFET_N_D56789G4S123" DNH0008A 1717.58,752.07 r0 bottom value=30V
Q450 "MOSFET_N_D12568G3S47" DQK0006C#1 2821.43,1063.64 r0 top value=25V
Q460 "MOSFET_N_D12568G3S47" DQK0006C#2 1674.7,2825 r90 bottom value=25V
Q470 "MOSFET_N_D12568G3S47" DQK0006C#1 3572.2,2356.19 r270 top value=25V
R50 "Resistor" 0402 2367.51,2003.26 r270 top value=0
R51 "Resistor" 0402 2219,1341 r90 top value=0
R52 "Resistor" 0402 1946.14,1828.86 r180 top value=0
R54 "Resistor" 0402 1946.76,1880 r180 top value=0
R55 "Resistor" 0402 1822.47,1670.86 r180 top value=0
R56 "Resistor" 0402 1969.08,1727.94 r180 bottom value=0
R57 "Resistor" 0402 2295.26,1342.44 r270 bottom value=100k
R58 "Resistor" 0402 1973.02,1557.94 r180 bottom value=100k
R59 "Resistor" 0402 1973.02,1502.94 r180 bottom value=100k
R60 "Resistor" 0402 1969.57,1617.94 r180 bottom value=100k
R61 "Resistor" 0402 2359.94,1340.47 r270 bottom value=100k
R62 "Resistor" 0402 1969.08,1672.94 r180 bottom value=100k
R63 "Resistor" 0402 2620,1729.54 r180 bottom value=100k
R64 "Resistor" 0402 2610,1625 r180 bottom value=100k
R65 "Resistor" 0402 2488.9,1340 r90 top value=100k
R66 "Resistor" 0402 2620,1685 r180 bottom value=100k
R67 "Resistor" 0402 2435.26,1342.44 r90 top value=100k
R210 "Resistor" 0402 2425,2018.22 r90 top value=0
R211 "Resistor" 0402 2875,1975 r0 top value=0
R212 "Resistor" 0402 2980,2084.83 r90 top value=0
R213 "CRCW040210K0FKED" 0402 2610,1860 r0 top value=10.0k
R214 "DNP" 0603 2750.48,2261.11 r0 top value=5.1
R215 "Resistor" 0402 2724.85,1726.76 r0 top value=0
R220 "Resistor" 0402 2138.2,1338.79 r270 top value=0
R221 "Resistor" 0402 2015,1335 r270 top value=0
R222 "Resistor" 0402 1810,1105 r270 top value=0
R223 "CRCW040210K0FKED" 0402 2058,1454 r180 top value=10.0k
R224 "DNP" 0603 2062.96,945 r180 top value=5.1
R225 "Resistor" 0402 1897,278 r270 bottom value=0
R226 "Resistor" 0402 1944.4,279 r270 bottom value=0
R230 "Resistor" 0402 2335,641.42 r270 bottom value=0
R240 "Resistor" 0402 3185,1425 r0 top value=0
R250 "Resistor" 0402 3405.64,883.19 r0 bottom value=0
R260 "Resistor" 0402 2251.12,1990.41 r90 top value=0
R261 "Resistor" 0402 2018,2012.6 r180 top value=0
R262 "Resistor" 0402 2017.49,2065 r180 top value=0
R263 "CRCW040210K0FKED" 0402 1945,1930 r180 bottom value=10.0k
R264 "DNP" 0603 1734.68,2218.63 r0 top value=5.1
R265 "Resistor" 0402 1786,2670 r90 bottom value=0
R401 "CRCW060310K0JNEA" 0603 1243.52,1219.05 r0 top value=10k
R402 "CRCW060310K0JNEA" 0603 1215,1566.17 r90 top value=10k
R403 "CRCW060310K0JNEA" 0603 1435,1455 r270 top value=10k
R404 "CRCW060310K0JNEA" 0603 1435,1320 r90 top value=10k
R421 "Resistor" 0402 1565,842.92 r0 top value=1.0
R422 "Resistor" 0402 1564.7,793.73 r0 top value=10.0k
R423 "Resistor" 1206 1535,605 r0 bottom value=1.00
R424 "Resistor" 1206 1530,711.24 r0 top value=1.00
R425 "Resistor" 0402 1482.76,575.04 r180 top value=49.9
R426 "Resistor" 0402 1758.62,506.5 r0 top value=49.9
R429 "Resistor" 1206 1530,711.24 r0 bottom value=1.00
R451 "Resistor" 0402 2711.61,996.61 r90 top value=1.0
R452 "Resistor" 0402 2656.61,996.61 r90 top value=10.0k
R453 "Resistor" 1206 2846.94,906.17 r90 bottom value=1.00
R454 "Resistor" 1206 2846.94,906.17 r90 top value=1.00
R455 "Resistor" 0402 2980,825 r270 top value=49.9
R456 "Resistor" 0402 3190,994.24 r90 top value=49.9
R461 "Resistor" 0402 1575,2773.63 r0 bottom value=1.0
R462 "Resistor" 0402 1635,2680 r90 bottom value=10.0k
R463 "Resistor" 1206 1495.12,2870.56 r0 bottom value=1.00
R464 "Resistor" 1206 1495.12,2870.56 r0 top value=1.00
R465 "Resistor" 0402 1540,2725 r0 top value=49.9
R466 "Resistor" 0402 1667.57,2391.35 r270 top value=49.9
R471 "Resistor" 0402 3539.5,2478.87 r270 top value=1.0
R472 "Resistor" 0402 3593.75,2477.49 r270 top value=10.0k
R473 "CRCW120610R0FKEA" 1206 3464.69,2275 r90 top value=10.0
R475 "CRCW040249R9FKED" 0402 3310,2295.44 r90 top value=49.9
R476 "CRCW040249R9FKED" 0402 3185,2003.26 r270 top value=49.9
R490 "CRCW06030000Z0EA" 0603 621.14,2290.44 r180 top value=0
R491 "CRCW0603100KFKEA" 0603 562.75,2536.66 r90 top value=100k
R493 "CRCW0603100KFKEA" 0603 1126.87,2177.03 r180 top value=100k
R494 "CRCW04024K22FKED" 0402 1297.24,2112.03 r0 top value=4.22k
R495 "CRCW040210K0FKED" 0402 1297.24,2167.03 r180 top value=10.0k
TP99 "5002" Keystone5002 2968.97,1892.92 r90 top
TP211 "5000" Keystone5000 2821.43,325 r90 top
TP212 "5001" Keystone5001 3285,420 r90 top
TP221 "5000" Keystone5000 3295,1821.97 r90 top
TP222 "5001" Keystone5001 3560,2747.17 r90 top
TP400 "5000" Keystone5000 120,2174.01 r90 top
TP401 "5001" Keystone5001 500,1285 r90 top
TP410 "5000" Keystone5000 2575,2630 r90 top
TP411 "5001" Keystone5001 3165,2670 r90 top
TP420 "5000" Keystone5000 1620,270 r90 top
TP421 "5001" Keystone5001 2200,248.94 r90 top
TP430 "5000" Keystone5000 2200,545 r90 top
TP431 "5001" Keystone5001 2655,470 r90 top
TP440 "5000" Keystone5000 3334.16,1305 r90 top
TP441 "5001" Keystone5001 3460,1765 r90 top
TP450 "5000" Keystone5000 3535.16,690 r90 top
TP451 "5001" Keystone5001 3583.87,1305 r90 top
TP460 "5000" Keystone5000 1595.83,2253.18 r90 top
TP461 "5001" Keystone5001 2192.97,2497.42 r90 top
TP490 "" Keystone5005 847.17,2685.44 r90 top
U50 "TPS65086100RSKR" RSK0064C 2280.89,1668.43 r90 top
U490 "TPS62173DSGR" DSG0008A 676.3,2445.48 r90 top
U491 "TPS74501PDRVR" DRV0006A 1181.87,2082.03 r180 top
ZZ1 "This Assembly Note is for PCB labels only" AssemblyNoteLabel 185,3938 r0 top
ZZ2 "These assemblies are ESD sensitive, ESD precautions shall be observed." AssemblyNote 185,3829.11 r0 top
ZZ3 "These assemblies must be clean and free from flux and all contaminants. Use of no clean flux is not acceptable." AssemblyNote 185,3740.56 r0 top
ZZ4 "These assemblies must comply with workmanship standards IPC-A-610 Class 2, unless otherwise specified." AssemblyNote 185,3652 r0 top

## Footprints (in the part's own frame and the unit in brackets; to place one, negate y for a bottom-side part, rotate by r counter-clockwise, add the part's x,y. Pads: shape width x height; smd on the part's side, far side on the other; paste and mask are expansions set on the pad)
0402 [mm] "0402 from SM-752 data"
  rect 0.8x0.6 smd: 1(-0.6,0) 2(0.6,0)
  silkscreen extent -1.22,-0.52 1.22,0.52, body extent -0.55,-0.3 0.55,0.3, height 0.6
0603 [mm] "0603 from SM-752 data"
  rect 1x0.95 smd: 1(-0.8,0) 2(0.8,0)
  silkscreen extent -1.52,-0.69 1.52,0.69, body extent -0.87,-0.47 0.87,0.47, height 1
0805 [mm] "0805 from SM-752 data"
  rect 1.3x1.5 smd: 1(-0.85,0) 2(0.85,0)
  silkscreen extent -1.72,-0.97 1.72,0.97, body extent -1.1,-0.72 1.1,0.72, height 1.45
0805_HV [mil] "0805 with 30mil clearance between pads"
  rect 50x63 smd: 1(-40,0) 2(40,0)
  silkscreen extent -74,-40 74,40, body extent -43,-29 43,29, height 57
1206 [mm] "1206 from SM-752 data"
  rect 1.3x1.85 smd: 1(-1.45,0) 2(1.45,0)
  silkscreen extent -2.4,-1.21 2.4,1.21, body extent -1.7,-0.9 1.7,0.9, height 1.35
1206_180 [mm] "1206_180"
  rect 1.1x1.6 smd: 1(-1.7,0) 2(1.7,0)
  silkscreen extent -0.9,-1 0.9,1, body extent -1.75,-0.95 1.75,0.95, height 1.8
AssemblyNote [mil] "Assembly Note"
AssemblyNoteLabel [mil] "Assembly Note for PCB Labels"
CE_Mark_5mm [mil] "Minimum text height for CE Mark"
  silkscreen extent -138,-98 138,98
CONN_5-146261-1 [mm] "Sullins"
  rect 1.5x1.5 hole 1.02: 1(-1.27,0)
  round 1.5 hole 1.02: 2(1.27,0)
  silkscreen extent -3.68,-1.27 2.54,1.27, body extent -2.51,-1.27 2.51,1.27, height 10.87
CONN_UFL-R-SMT-1 [mm] "Hirose recommended land pattern http://www.hirose.co.jp/cataloge_hp/e32119372.pdf 2009.2"
  rect 1.05x1 smd paste-0.1 mask-0.1: 1(-1.525,0)
  rect 2x0.9 on Top Paste: 2(0,1.5) 3(0,-1.5)
  rect 2x0.9 on Top Solder: 2(0,1.5) 3(0,-1.5)
  rect 2.2x1.05 smd paste-2 mask-2: 2(0,1.475) 3(0,-1.475)
  Top Layer keep-out region: -0.8,-0.7 1.1,-0.7 1.1,0.7 -0.8,0.7
  silkscreen extent -1.7,-1.7 1.7,1.7, body extent -1.55,-1.5 1.55,1.5, height 1.27
DNH0008A [mm] "VSONP-8"
  rrect50% 0.7x0.4 smd paste-0.05 mask-0.05: 1(-1.55,0.975) 2(-1.55,0.325) 3(-1.55,-0.325) 4(-1.55,-0.975) 5(1.55,-0.975) 6(1.55,-0.325) 7(1.55,0.325) 8(1.55,0.975)
  rrect4% 2.51x2.55 smd paste-1.5 mask-1.5: 9(0.645,0)
  rrect14% 0.705x1.125 on Bottom Paste: 9A(-0.208,0.662) 9B(0.697,0.662) 9C(-0.208,-0.663) 9D(0.697,-0.663)
  silkscreen extent -1.62,-1.7 1.62,1.7, body extent -1.65,-1.66 1.65,1.66, height 0.91
DQK0006C#1 [mm] "WSON"
  rrect12% 0.9x0.86 on Top Paste: 0(0,0.325)
  rrect34% 0.7x0.29 on Top Paste: 0(0.095,-0.65)
  rrect33% 0.45x0.3 smd: 1(-0.975,0.65) 2(-0.975,0) 3(-0.975,-0.65) 4(0.975,-0.65) 5(0.975,0) 6(0.975,0.65)
  rrect33% 0.75x0.3 smd paste-0.15: 7(0.095,-0.65)
  rrect11% 1x0.95 smd paste-0.5: 8(0,0.325)
  silkscreen extent -1.15,-1.15 1.15,1.15, body extent -1,-1 1,1, height 0.82
DQK0006C#2 [mm] "WSON"
  rrect12% 0.9x0.86 on Bottom Paste: 0(0,0.325)
  rrect34% 0.7x0.29 on Bottom Paste: 0(0.095,-0.65)
  rrect33% 0.45x0.3 smd: 1(-0.975,0.65) 2(-0.975,0) 3(-0.975,-0.65) 4(0.975,-0.65) 5(0.975,0) 6(0.975,0.65)
  rrect33% 0.75x0.3 smd paste-0.15: 7(0.095,-0.65)
  rrect11% 1x0.95 smd paste-0.5: 8(0,0.325)
  silkscreen extent -1.15,-1.15 1.15,1.15, body extent -1,-1 1,1, height 0.82
DRV0006A [mm] "SON, 6-Leads, Body 2x2mm, Pitch 0.65mm, Thermal Pad 1.6x1mm, TI Recommended"
  rrect33% 0.45x0.3 smd: 1(-0.975,0.65) 2(-0.975,0) 3(-0.975,-0.65) 4(0.975,-0.65) 5(0.975,0) 6(0.975,0.65)
  rrect14% 1x0.7 on Top Paste: 7(0,0.45) 7(0,-0.45)
  rrect10% 1x1.6 smd paste-0.5: 7(0,0)
  silkscreen extent -1.05,-1.2 1.05,1.2, body extent -1.05,-1.05 1.05,1.05, height 0.81
DSG0008A [mm] "SON, 8-Leads, Body 2x2mm, Pitch 0.5mm, Thermal Pad 1.6x0.9mm, TI Recommended"
  rrect40% 0.5x0.25 smd: 1(-0.95,0.75) 2(-0.95,0.25) 3(-0.95,-0.25) 4(-0.95,-0.75) 5(0.95,-0.75) 6(0.95,-0.25) 7(0.95,0.25) 8(0.95,0.75)
  rrect14% 0.9x0.7 on Top Paste: 9(0,0.45) 9(0,-0.45)
  rrect11% 0.9x1.6 smd paste-0.45: 9(0,0)
  silkscreen extent -1.07,-1.15 1.07,1.15, body extent -1,-1 1,1, height 0.77
Fiducial10-20 [mm]
  round 1 smd mask+0.5: 1(0,0)
  Top Layer keep-out circle w1.178: c0,0 r0.5
HCB65-550X [mm] "SMD, 2-Leads, Body 5.5x5.7mm"
  rect 2x2.5 smd: 1(-1.9,0) 2(1.9,0)
  silkscreen extent -2.75,-2.85 2.75,2.85, body extent -2.75,-2.85 2.75,2.85, height 4.6
Keystone5000 [mil] "For Keystone 500x miniature loop terminals"
  round 80 hole 40: 1(0,0)
  silkscreen extent -52,-52 52,52, body extent -49,-49 49,49, height 182
Keystone5001 [mil] "For Keystone 500x miniature loop terminals"
  round 80 hole 40: 1(0,0)
  silkscreen extent -52,-52 52,52, body extent -49,-49 49,49, height 182
Keystone5002 [mil] "For Keystone 500x miniature loop terminals"
  round 80 hole 40: 1(0,0)
  silkscreen extent -52,-52 52,52, body extent -49,-49 49,49, height 182
Keystone5005 [mil] "Keystone Compact loops"
  round 87 hole 63: 1(0,0)
  silkscreen extent -70,-70 70,70, body extent -63,-63 62,63, height 225
Keystone_1902C [mil] "Hex Standoff, 4-40 threaded, nylon"
  round 1 on Mech4: 0(0,0)
  body extent -145,-126 146,126, height 501
Label_650x200 [mil] "Thermal Transfer Label"
  round 1 on Mech14: 0(0,0)
  silkscreen extent -325,-100 325,100, body extent -325,-100 325,100, height 1
MPC0005A_100um [mm] "Texas Instruments - 100um stencil recommendation"
  rect 0.32x0.32 smd paste-0.16 mask+0.076: 1(-0.503,0.918) 4(-0.503,-0.718)
  rect 0.706x0.401 smd paste-0.25 mask+0.076: 2(0.31,0.918)
  rect 0.703x0.912 smd paste-0.36 mask+0.076: 3(0.312,-0.423)
  rect 2.5x0.25 smd paste-0.125 mask+0.076: 5(0,-1.375)
  Top Layer region: -0.663,0.032 -0.663,-0.26 0.037,-0.26 0.037,0.032
  silkscreen extent -1.5,-1.75 1.5,1.75, body extent -1.3,-1.55 1.3,1.55, height 0.49
"NY PMS 440 0025 PH" [mm] "4-40 nylon screw and mounting hole"
  round 8 hole 3.2: 1(0,0)
  body extent -3.3,-3.3 3.3,3.3, height 2.69
On-Shore_ED120_2DS [mm] "ONSHORE"
  rrect5% 2x2 hole 1.25: 1(-2.54,0)
  round 2 hole 1.25: 2(2.54,0)
  silkscreen extent -5.6,-4 5.12,5, body extent -5.78,-4 5.08,5, height 13
Phoenix_1935776 [mm] "Terminal Block, 2x1, 5mm, TH"
  rect 1.8x1.8 hole 1.3: 1(-2.5,0)
  round 1.8 hole 1.3: 2(2.5,0)
  silkscreen extent -5.3,-4.5 5,4.5, body extent -5,-4.5 5,4.5, height 13.5
RSK0064C [mm] "QFN, 64-Leads, Body 8x8mm, Pitch 0.4mm"
  oval 0.7x0.2 smd: 1(-3.85,3) 2(-3.85,2.6) 3(-3.85,2.2) 4(-3.85,1.8) 5(-3.85,1.4) 6(-3.85,1) 7(-3.85,0.6) 8(-3.85,0.2) 9(-3.85,-0.2) 10(-3.85,-0.6) 11(-3.85,-1) 12(-3.85,-1.4) 13(-3.85,-1.8) 14(-3.85,-2.2) 15(-3.85,-2.6) 16(-3.85,-3) 33(3.85,-3) 34(3.85,-2.6) 35(3.85,-2.2) 36(3.85,-1.8) 37(3.85,-1.4) 38(3.85,-1) 39(3.85,-0.6) 40(3.85,-0.2) 41(3.85,0.2) 42(3.85,0.6) 43(3.85,1) 44(3.85,1.4) 45(3.85,1.8) 46(3.85,2.2) 47(3.85,2.6) 48(3.85,3)
  oval 0.2x0.7 smd: 17(-3,-3.85) 18(-2.6,-3.85) 19(-2.2,-3.85) 20(-1.8,-3.85) 21(-1.4,-3.85) 22(-1,-3.85) 23(-0.6,-3.85) 24(-0.2,-3.85) 25(0.2,-3.85) 26(0.6,-3.85) 27(1,-3.85) 28(1.4,-3.85) 29(1.8,-3.85) 30(2.2,-3.85) 31(2.6,-3.85) 32(3,-3.85) 49(3,3.85) 50(2.6,3.85) 51(2.2,3.85) 52(1.8,3.85) 53(1.4,3.85) 54(1,3.85) 55(0.6,3.85) 56(0.2,3.85) 57(-0.2,3.85) 58(-0.6,3.85) 59(-1,3.85) 60(-1.4,3.85) 61(-1.8,3.85) 62(-2.2,3.85) 63(-2.6,3.85) 64(-3,3.85)
  rect 5.7x5.7 smd paste-5.7: 65(0,0)
  silkscreen extent -4.18,-4.18 4.18,4.18, body extent -4.08,-4.08 4.08,4.08, height 1.01
SM_RADIAL_10BMM [mm] "Nichicon 10x10"
  rect 4x2.5 smd: 1(-4,0) 2(4,0)
  silkscreen extent -5.25,-5.25 5.25,5.25, body extent -5.25,-5.25 5.25,5.25, height 10.5
SOT-23 [mm] "SOT23, 3-Leads, Body 2.9x1.3mm, Pitch 0.95mm, Lead Span 2.5mm, IPC Medium Density"
  rrect50% 1x0.6 smd: 1(-1.2,0.95) 2(-1.2,-0.95) 3(1.2,0)
  silkscreen extent -1.63,-1.5 0.7,1.5, body extent -1.16,-1.45 1.21,1.45, height 1
TI_Stacked_Overlay_Small [mil]
  silkscreen extent -418,-98 418,98
TSW-102-07-G-S [mm] "Samtec 100mil, 1x2, 230 mil above insulator"
  rrect50% 1.65x1.65 hole 1.016: 1(-1.27,0)
  round 1.65 hole 1.016: 2(1.27,0)
  silkscreen extent -3.17,-1.27 2.54,1.27, body extent -2.54,-1.27 2.54,1.27, height 8.38
TSW-103-07-G-S [mm] "Samtec 100mil, 1x3, 230 mil above insulator"
  rrect50% 1.65x1.65 hole 1.016: 1(-2.54,0)
  round 1.65 hole 1.016: 2(0,0) 3(2.54,0)
  body extent -3.81,-1.27 3.81,1.27, height 8.38
TSW-105-07-G-D [mm] "Samtec 100mil, 2x5, 230 mil above insulator"
  rrect6% 1.65x1.65 hole 1.016: 1(-5.08,-1.27)
  round 1.65 hole 1.016: 2(-5.08,1.27) 3(-2.54,-1.27) 4(-2.54,1.27) 5(0,-1.27) 6(0,1.27) 7(2.54,-1.27) 8(2.54,1.27) 9(5.08,-1.27) 10(5.08,1.27)
  silkscreen extent -7.37,-2.54 6.35,2.54, body extent -6.35,-2.54 6.35,2.54, height 8.38
TSW-105-07-X-S [mm] "Samtec 100mil, 1x5, 230 mil above insulator"
  rrect6% 1.65x1.65 hole 1.016: 1(-5.08,-0.025)
  round 1.65 hole 1.016: 2(-2.54,0) 3(0,0) 4(2.54,0) 5(5.08,0)
  silkscreen extent -7.05,-1.25 6.37,1.25, body extent -6.35,-1.27 6.35,1.27, height 8.38
WE-MAPI_3020 [mm] "SMD, 2-Leads, Body 3.2x3.2mm"
  rect 1.3x3.4 smd: 1(-1.05,0) 2(1.05,0)
  silkscreen extent -0.1,-1.6 0.1,1.6, body extent -1.6,-1.6 1.6,1.6, height 2
WEEE_Minimum [mil] "WEEElie bin"
  silkscreen extent -95,-172 99,104
Wurth_691214110002 [mm] "Receptacle, 3.5mm, 2x1, TH"
  rect 1.8x1.8 hole 1.3: 1(-1.75,0)
  round 1.8 hole 1.3: 2(1.75,0)
  silkscreen extent -3.8,-3.4 3.5,4, body extent -3.9,-3.4 3.5,4, height 8.5
XAL4020 [mm] "Coilcraft XAL4020 01/14/18"
  rrect10% 0.98x3.4 smd: 1(-1.185,0) 2(1.185,0)
  body extent -2.15,-2.15 2.15,2.15, height 2.11
XPL2010 [mm] "Coilcraft recommended land pattern Document 646-2 Revised 3/28/11"
  rect 1.04x2.2 smd: 1(-0.725,0) 2(0.725,0)
  silkscreen extent -1.52,-1.4 1.52,1.4, body extent -1.05,-1.1 1.05,1.1, height 1

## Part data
C50 C51: library part CMP-0006341-2, "CAP, CERM, 2.2 uF, 6.3 V, +/- 10%, X5R, 0402", Cap_Case=0402, Manufacturer=Samsung, PartNumber=CL05A225KQ5NNNC, Supplier Part Number 1=1276-1172-1-ND, TempCo=X5R, Tolerance_%=10%, Value1=Unknown, Value2=6.3V, ValueDisplayed=2.2uF
C52 C53 C54 C55: library part CMP-0006564-2, "CAP, CERM, 10 uF, 10 V, +/- 20%, X5R, 0402", Cap_Case=0402, Manufacturer=MuRata, TempCo=X5R, Tolerance_%=20%, Value1=Unknown, Value2=10V, ValueDisplayed=10uF
C56 C57 C62 C63 C65: library part CMP-0006563-2, "CAP, CERM, 1 uF, 10 V, +/- 10%, X5R, 0402", Cap_Case=0402, Manufacturer=MuRata, PartNumber=GRM155R61A105KE15D, Supplier Part Number 1=490-3890-1-ND, TempCo=X5R, Tolerance_%=10%, Value1=Unknown, Value2=10V, ValueDisplayed=1uF
C58: library part CMP-0006619-2, "CAP, CERM, 1 uF, 35 V, +/- 10%, X5R, 0402", Cap_Case=0402, Manufacturer=MuRata, PartNumber=GRM155R6YA105KE11D, Supplier Part Number 1=490-10019-1-ND, TempCo=X5R, Tolerance_%=10%, Value1=Unknown, Value2=35V, ValueDisplayed=1uF
C59 C64 C212 C217 C222 C232 C242 C254 C262 C268 C280: library part CMP-0006562-2, "CAP, CERM, 0.1 uF, 10 V, +/- 10%, X5R, 0402", Cap_Case=0402, Manufacturer=MuRata, PartNumber=GRM155R61A104KA01D, Supplier Part Number 1=490-1318-1-ND, TempCo=X5R, Tolerance_%=10%, Value1=Unknown, Value2=10V, ValueDisplayed=0.1uF
C60 C61: library part CMP-0007330-5, "CAP, CERM, 4.7 uF, 10 V, +/- 20%, X5R, 0603", Cap_Case=0603, Manufacturer=MuRata, PartNumber=GRM188R61A475ME15, Supplier Part Number 1=490-10478-1-ND, TempCo=X5R, Tolerance_%=20%, Value1=Unknown, Value2=10V, ValueDisplayed=4.7uF
C210 C211 C220 C221 C260 C261: library part CMP-0007827-2, "CAP, CERM, 22 uF, 16 V, +/- 20%, X5R, 0805", Cap_Case=0805, Manufacturer=TDK, Supplier Part Number 1=445-7647-1-ND, TempCo=X5R, Tolerance_%=20%, Value1=Unknown, Value2=16V, ValueDisplayed=22uF
C213 C215 C223 C225 C226 C227 C228 C230 C240 C250 C251 C252 C263 C265 C266: library part CMP-0008284-2, "CAP, CERM, 47 uF, 6.3 V, +/- 20%, X5R, 0805", Cap_Case=0805, Manufacturer=MuRata, Supplier Part Number 1=490-9960-1-ND, TempCo=X5R, Tolerance_%=20%, Value1=Unknown, Value2=6.3V, ValueDisplayed=47uF
C214 C224 C264: library part CMP-0007264-4, "CAP, CERM, 330 pF, 100 V, +/- 5%, C0G/NP0, 0603", Cap_Case=0603, Manufacturer=MuRata, PartNumber=GRM1885C2A331JA01D, Supplier Part Number 1=490-1363-1-ND, TempCo=C0G/NP0, Tolerance_%=5%, Value1=Unknown, Value2=100V, ValueDisplayed=330pF
C216 C229 C231 C241 C253 C267: library part CMP-0007312-5, "CAP, CERM, 4.7 uF, 6.3 V, +/- 20%, X5R, 0603", Cap_Case=0603, Manufacturer=MuRata, PartNumber=GRM188R60J475ME19D, Supplier Part Number 1=490-5421-1-ND, TempCo=X5R, Tolerance_%=20%, Value1="0.001 ohm", Value2=6.3V, ValueDisplayed=4.7uF
C401: library part CMP-0006802-4, "CAP, CERM, 0.1 uF, 50 V, +/- 10%, X7R, 0603", Cap_Case=0603, Manufacturer=AVX, Supplier Part Number 1=478-5052-1-ND, TempCo=X7R, Tolerance_%=10%, Value1=Unknown, Value2=50V, ValueDisplayed=0.1uF
C402: library part CMP-0008946-2, "CAP, CERM, 22 uF, 16 V, +/- 10%, X5R, 1206", Cap_Case=1206, Manufacturer=MuRata, Supplier Part Number 1=GRM31CR61C226KE15L-ND, TempCo=X5R, Tolerance_%=10%, Value1=Unknown, Value2=16V, ValueDisplayed=22uF
C403: library part CMP-0012587-3, "CAP, Polymer Hybrid, 270 uF, 35 V, +/- 20%, 20 ohm, 10x10 SMD", Manufacturer=Panasonic, Supplier Part Number 1=P15453CT-ND, Tolerance_%=20%, Value1="20 ohm", Value2=35V, ValueDisplayed=270uF
C412: library part CMP-0007822-2, "CAP, CERM, 22 uF, 6.3 V, +/- 20%, X5R, 0805", Cap_Case=0805, Manufacturer=TDK, Supplier Part Number 1=445-7678-1-ND, TempCo=X5R, Tolerance_%=20%, Value1=Unknown, Value2=6.3V, ValueDisplayed=22uF
C421 C422 C452: library part CMP-0006356-2, "CAP, CERM, 0.1 uF, 50 V, +/- 10%, X7R, AEC-Q200 Grade 1, 0402", Cap_Case=0402, Manufacturer=MuRata, Supplier Part Number 1=490-10672-1-ND, TempCo=X7R, Tolerance_%=10%, Value1=Unknown, Value2=50V, ValueDisplayed=0.1uF
C451 C461 C462 C471 C472: library part CMP-0006356-2, "CAP, CERM, 0.1 uF, 50 V, +/- 10%, X7R, AEC-Q200 Grade 1, 0402", Cap_Case=0402, Manufacturer=MuRata, PartNumber=GCM155R71H104KE02D, Supplier Part Number 1=490-10672-1-ND, TempCo=X7R, Tolerance_%=10%, Value1=Unknown, Value2=50V, ValueDisplayed=0.1uF
C490: library part CMP-0007007-5, "CAP, CERM, 10 uF, 25 V, +/- 20%, X5R, 0603", Cap_Case=0603, Manufacturer=TDK, Supplier Part Number 1=445-9015-1-ND, TempCo=X5R, Tolerance_%=20%, Value1="0.004639 ohm", Value2=25V, ValueDisplayed=10uF
C491: library part CMP-0007828-2, "CAP, CERM, 10 uF, 25 V, +/- 10%, X5R, 0805", Cap_Case=0805, Manufacturer=TDK, Supplier Part Number 1=445-5984-1-ND, TempCo=X5R, Tolerance_%=10%, Value1=Unknown, Value2=25V, ValueDisplayed=10uF
C493 C494: library part CMP-0007091-5, "CAP, CERM, 2.2 uF, 10 V, +/- 10%, X5R, AEC-Q200 Grade 3, 0603", Cap_Case=0603, Manufacturer=TDK, Supplier Part Number 1=445-12444-1-ND, TempCo=X5R, Tolerance_%=10%, Value1=Unknown, Value2=10V, ValueDisplayed=2.2uF
D99: library part CMP-0028453-2, "Diode, Schottky, 30 V, 0.2 A, SOT-23", Manufacturer="Diodes Inc.", Value1=0.2A, Value2=0.65V
FID1 FID2 FID3: library part CMP-0077181-1, "Fiducial mark.  There is nothing to buy or mount.", Manufacturer=N/A
H1 H2 H3 H4: library part CMP-0003617-1, "Machine Screw, Round, #4-40 x 1/4, Nylon, Philips panhead", Manufacturer="B&F Fastener Supply", Supplier Part Number 1=H542-ND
